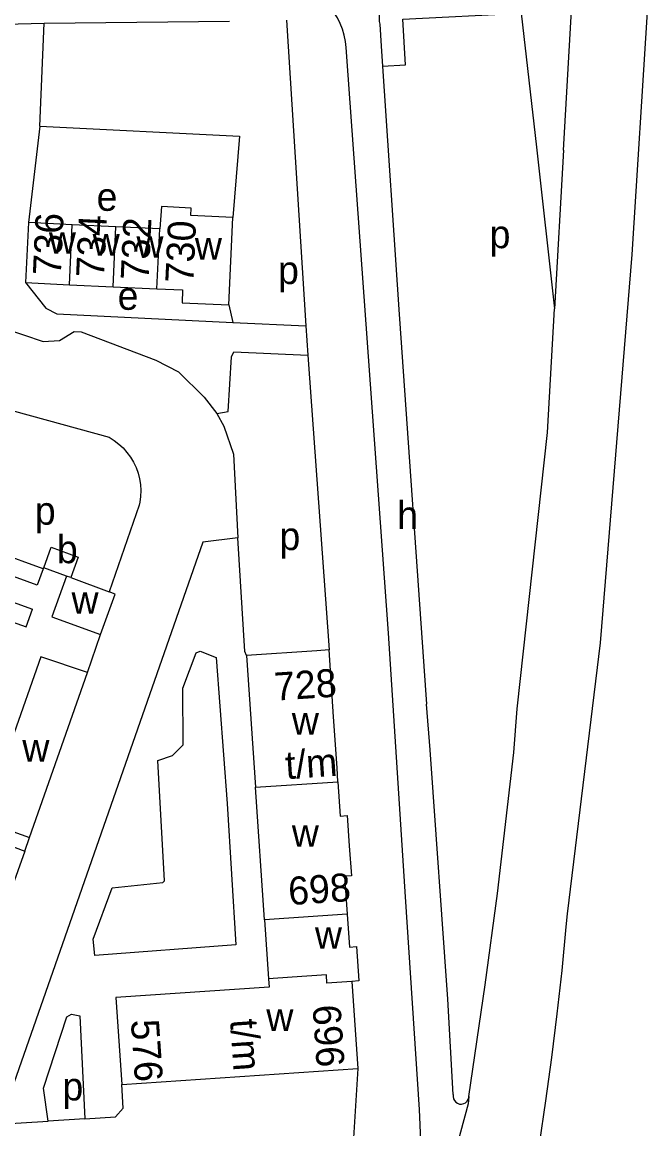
# Model space of a CAD drawing. Extents: x 159294 to 161936, y 384538 to 386517.
# Drawn here: x 161759 to 161848.3, y 385198.5 to 385356.4 of the extents above; entities that cross this region are included whole.
import ezdxf

# ---------------------------------------------------------------- set-up
doc = ezdxf.new("R2010")
doc.units = 0
for name, color, linetype in [('BLT_Basislijn', 7, 'Continuous'), ('BLT_Bebouwing', 7, 'Continuous'), ('BLT_Centroide', 7, 'Continuous'), ('BLT_Huisnummer', 7, 'Continuous'), ('BLT_Huisnummer_ tussenligend', 7, 'Continuous'), ('BLT_Huisnummer_reeks', 7, 'Continuous'), ('BLT_Onderverdeling_panden', 7, 'Continuous'), ('BLT_Vlakafsluiter', 7, 'Continuous')]:
    doc.layers.add(name, color=color, linetype=linetype)

msp = doc.modelspace()

# ---------------------------------------------------------------- linework, layer by layer
at = {"layer": 'BLT_Basislijn'}
for p, q in [((161846.09, 385323.27), (161848.34, 385358.68)), ((161762.16, 385356.28), (161788.6, 385356.6)), ((161796.72, 385356.7), (161799.51, 385313.11)), ((161761.51, 385341.58), (161762.16, 385356.28)), ((161810.05, 385356.17), (161810.26, 385353.03)), ((161811.3, 385269.25), (161805.25, 385352.81)), ((161810.26, 385353.03), (161810.45, 385350.17)), ((161810.45, 385350.17), (161812.77, 385315.42)), ((161761.51, 385341.58), (161759.89, 385327.82)), ((161788.5, 385316.09), (161789.09, 385313.59)), ((161812.77, 385315.42), (161816.75, 385259.11)), ((161789.09, 385313.59), (161799.51, 385313.11)), ((161799.51, 385313.11), (161799.8, 385308.91)), ((161799.8, 385308.91), (161802.83, 385266.84)), ((161757.88, 385300.91), (161771.4, 385297.19)), ((161775.71, 385287.49), (161771.42, 385275.13)), ((161761.99, 385278.43), (161762.08, 385278.58)), ((161768.34, 385263.61), (161770.2, 385269.06)), ((161759.38, 385238.14), (161760.06, 385240.09)), ((161806.91, 385207.1), (161805.99, 385191.99)), ((161755.69, 385199.14), (161762.7, 385199.57)), ((161767.95, 385199.92), (161762.7, 385199.57))]:
    msp.add_line(p, q, dxfattribs=at)
for points in [[(161805.25, 385352.81), (161805.16, 385353.69), (161804.99, 385354.56), (161804.74, 385355.42), (161804.41, 385356.24), (161804.02, 385357.04), (161803.55, 385357.79), (161803.02, 385358.5), (161802.42, 385359.16), (161801.77, 385359.76), (161801.07, 385360.3), (161800.32, 385360.78), (161799.53, 385361.18), (161798.7, 385361.52), (161797.48, 385361.89)], [(161812.4, 385361.34), (161811.39, 385360.48), (161810.98, 385360.01), (161810.63, 385359.5), (161810.35, 385358.95), (161810.15, 385358.37), (161810.02, 385357.76), (161809.96, 385357.15), (161809.99, 385356.53), (161810.05, 385356.17)], [(161810.45, 385350.17), (161813.74, 385350.33), (161813.35, 385356.85), (161830.26, 385357.74)], [(161830.26, 385357.74), (161832.42, 385338.59), (161835.01, 385315.51)], [(161836.3, 385338.19), (161837.43, 385358.11)], [(161755.37, 385356.09), (161756.58, 385356.13), (161762.16, 385356.28)], [(161761.51, 385341.58), (161790.05, 385340.18), (161789.08, 385328.55)], [(161730.52, 385325.45), (161731.07, 385323.59), (161733.29, 385321.42), (161753.5, 385313.73), (161761.99, 385310.86), (161764.31, 385310.98), (161766.44, 385312.3), (161767.4, 385312.23), (161778.08, 385308.18), (161781.33, 385306.51), (161785, 385302.9), (161786.8, 385300.6)], [(161836.86, 385229.15), (161841.56, 385267.85), (161846.09, 385323.27)], [(161759.49, 385319.26), (161762.39, 385315.6), (161763.96, 385314.8), (161789.09, 385313.59)], [(161829.68, 385258.42), (161834.01, 385297.86), (161835.01, 385315.51)], [(161786.8, 385300.6), (161788.43, 385300.88), (161788.9, 385308.69), (161789.24, 385309.4), (161799.8, 385308.91)], [(161786.8, 385300.6), (161787.77, 385298.77), (161789.15, 385294.77), (161789.8, 385282.85)], [(161771.4, 385297.19), (161772.12, 385296.74), (161772.78, 385296.23), (161773.4, 385295.66), (161773.96, 385295.03), (161774.46, 385294.36), (161774.89, 385293.63), (161775.25, 385292.88), (161775.54, 385292.08), (161775.75, 385291.27), (161775.88, 385290.44), (161775.93, 385289.6), (161775.91, 385288.76), (161775.8, 385287.93), (161775.71, 385287.49)], [(161789.8, 385282.85), (161784.79, 385282.24), (161755.69, 385199.14)], [(161791.04, 385266.05), (161790.77, 385266.6), (161789.8, 385282.85)], [(161815.74, 385201.24), (161813.74, 385231.59), (161811.3, 385269.25)], [(161788.27, 385244.91), (161789.5, 385224.77), (161769.37, 385223.25), (161769.15, 385225.57), (161771.83, 385232.88), (161779.1, 385233.63), (161779.32, 385233.9), (161778.37, 385251.08), (161780.47, 385251.79), (161781.99, 385253.29), (161781.94, 385261.38), (161783.84, 385266.44), (161784.41, 385266.66), (161786.71, 385265.74), (161788.27, 385244.91)], [(161820.55, 385203.38), (161819.77, 385216.99), (161817.24, 385252.59), (161816.75, 385259.11)], [(161822.78, 385203.09), (161825.11, 385219.04), (161826.86, 385232.07), (161829.2, 385252.2), (161829.68, 385258.42)], [(161824.2, 385153.45), (161825.67, 385159.53), (161827.07, 385165.62), (161828.39, 385171.72), (161829.62, 385177.85), (161830.79, 385183.99), (161831.87, 385190.14), (161832.87, 385196.31), (161833.79, 385202.49), (161834.64, 385208.68), (161835.4, 385214.88), (161836.09, 385221.09), (161836.69, 385227.31), (161836.86, 385229.15)], [(161762.7, 385199.57), (161762.02, 385204.29), (161765.38, 385214.48), (161766.03, 385214.85), (161767.21, 385214.63), (161767.95, 385199.92)], [(161767.95, 385199.92), (161772.33, 385200.19), (161773.44, 385201.46), (161773.23, 385204.8)], [(161820.55, 385203.38), (161820.52, 385203.08), (161820.58, 385202.79), (161820.71, 385202.52), (161820.91, 385202.29), (161821.16, 385202.13), (161821.45, 385202.03), (161821.75, 385202.02), (161822.04, 385202.09), (161822.31, 385202.22), (161822.53, 385202.43), (161822.68, 385202.68), (161822.77, 385202.97), (161822.78, 385203.09)], [(161813.9, 385169.7), (161814.43, 385173.06), (161814.88, 385176.43), (161815.25, 385179.81), (161815.54, 385183.19), (161815.75, 385186.58), (161815.88, 385189.98), (161815.93, 385193.38), (161815.9, 385196.77), (161815.79, 385200.17), (161815.74, 385201.24)]]:
    msp.add_lwpolyline(points, dxfattribs=at)
at = {"layer": 'BLT_Bebouwing'}
for p, q in [((161788.5, 385316.09), (161789.08, 385328.55)), ((161759.89, 385327.82), (161759.49, 385319.26)), ((161766.14, 385327.53), (161759.89, 385327.82)), ((161772.39, 385327.24), (161766.14, 385327.53)), ((161778.64, 385326.95), (161772.39, 385327.24)), ((161759.49, 385319.26), (161765.74, 385318.97)), ((161765.74, 385318.97), (161771.99, 385318.68)), ((161771.99, 385318.68), (161778.24, 385318.39)), ((161761.99, 385278.43), (161751.36, 385282.27)), ((161765.33, 385277.39), (161762.08, 385278.58)), ((161765.94, 385277.17), (161765.33, 385277.39)), ((161765.94, 385277.17), (161771.42, 385275.13)), ((161755.15, 385274.59), (161760.48, 385272.68)), ((161803.47, 385257.31), (161802.83, 385266.84)), ((161759.38, 385238.14), (161757.4, 385232.52)), ((161793.61, 385228.31), (161794.18, 385219.9)), ((161806.06, 385219.53), (161806.91, 385207.1)), ((161794.26, 385218.73), (161772.38, 385217.24)), ((161772.38, 385217.24), (161773.23, 385204.8)), ((161790.07, 385205.95), (161798.49, 385206.53)), ((161798.49, 385206.53), (161806.91, 385207.1)), ((161773.23, 385204.8), (161781.65, 385205.38)), ((161781.65, 385205.38), (161790.07, 385205.95))]:
    msp.add_line(p, q, dxfattribs=at)
for points in [[(161789.08, 385328.55), (161783.08, 385328.83), (161783.13, 385329.91), (161778.88, 385330.11), (161778.64, 385326.95)], [(161778.24, 385318.39), (161781.91, 385318.22), (161781.83, 385316.4), (161788.5, 385316.09)], [(161762.08, 385278.58), (161763.15, 385281.49), (161767, 385280.08), (161765.94, 385277.17)], [(161761.99, 385278.43), (161761.15, 385276.1), (161756.32, 385277.84), (161755.15, 385274.59)], [(161765.33, 385277.39), (161763.25, 385271.56), (161770.2, 385269.06)], [(161770.2, 385269.06), (161772.27, 385274.78), (161771.42, 385275.13)], [(161754.34, 385272), (161759.56, 385270.13), (161760.48, 385272.68)], [(161802.83, 385266.84), (161801.08, 385266.73), (161791.04, 385266.05)], [(161768.34, 385263.61), (161761.67, 385265.85), (161757.53, 385254.07), (161755.95, 385254.64), (161751.83, 385243.03), (161760.06, 385240.09)], [(161791.04, 385266.05), (161792.32, 385247.23)], [(161760.06, 385240.09), (161768.34, 385263.61)], [(161804.09, 385248.02), (161803.96, 385250), (161803.47, 385257.31)], [(161804.09, 385248.02), (161804.42, 385243.13), (161805.42, 385243.2), (161805.71, 385238.87)], [(161793.61, 385228.31), (161792.32, 385247.23)], [(161751.1, 385234.95), (161753.17, 385240.43), (161759.38, 385238.14)], [(161805.71, 385238.87), (161806, 385234.62), (161805, 385234.55), (161805.39, 385229.11)], [(161805.39, 385229.11), (161805.73, 385224.42), (161806.73, 385224.49), (161807.07, 385219.6), (161806.06, 385219.53)]]:
    msp.add_lwpolyline(points, dxfattribs=at)
at = {"layer": 'BLT_Onderverdeling_panden'}
for p, q in [((161765.74, 385318.97), (161766.14, 385327.53)), ((161771.99, 385318.68), (161772.39, 385327.24)), ((161778.24, 385318.39), (161778.64, 385326.95)), ((161792.32, 385247.23), (161804.09, 385248.02)), ((161805.39, 385229.11), (161793.61, 385228.31))]:
    msp.add_line(p, q, dxfattribs=at)
for points in [[(161797.56, 385220.13), (161794.18, 385219.9)], [(161794.18, 385219.9), (161794.26, 385218.73)], [(161806.06, 385219.53), (161802.51, 385219.29), (161802.43, 385220.47), (161797.56, 385220.13)]]:
    msp.add_lwpolyline(points, dxfattribs=at)
at = {"layer": 'BLT_Vlakafsluiter'}
msp.add_line((161836.3, 385338.19), (161835.01, 385315.51), dxfattribs=at)
msp.add_lwpolyline([(161822.78, 385203.09), (161822.68, 385202.07), (161813.9, 385169.7)], dxfattribs=at)

# ---------------------------------------------------------------- texts
at = {"layer": 'BLT_Centroide'}
for s, p in [('e', (161769.63, 385329.51)), ('p', (161825.74, 385324.18)), ('w', (161762.81, 385323.39)), ('w', (161769.06, 385323.11)), ('w', (161775.31, 385322.81)), ('w', (161783.66, 385322.56)), ('p', (161795.53, 385319.06)), ('e', (161772.63, 385315.38)), ('p', (161760.8, 385284.71)), ('h', (161812.54, 385284.09)), ('p', (161795.73, 385281.09)), ('b', (161763.95, 385279.22)), ('w', (161766.04, 385272)), ('w', (161797.5, 385254.75)), ('w', (161759.02, 385250.89)), ('w', (161797.5, 385238.75)), ('w', (161800.8, 385224.19)), ('w', (161793.86, 385212.45)), ('p', (161764.74, 385202.54))]:
    msp.add_text(s, height=4, dxfattribs=at).set_placement(p)
at = {"layer": 'BLT_Huisnummer'}
for s, p in [('736', (161764.51, 385320.21)), ('730', (161783.42, 385319.12))]:
    msp.add_text(s, height=4, rotation=87.3313, dxfattribs=at).set_placement(p)
at = {"layer": 'BLT_Huisnummer_ tussenligend'}
for s, p in [('734', (161770.68, 385319.92)), ('732', (161777.05, 385319.54))]:
    msp.add_text(s, height=4, rotation=87.3313, dxfattribs=at).set_placement(p)
at = {"layer": 'BLT_Huisnummer_reeks'}
for s, rotation, p in [('728', 3.8328, (161795.11, 385259.59)), ('t/m', 3.8317, (161796.69, 385248.39)), ('698', 3.8947, (161797.12, 385230.41)), ('696', 273.9028, (161800.45, 385216.08)), ('576', 273.9028, (161774.51, 385213.99)), ('t/m', 273.9022, (161788.68, 385214.05))]:
    msp.add_text(s, height=4, rotation=rotation, dxfattribs=at).set_placement(p)

doc.saveas('drawing.dxf')
